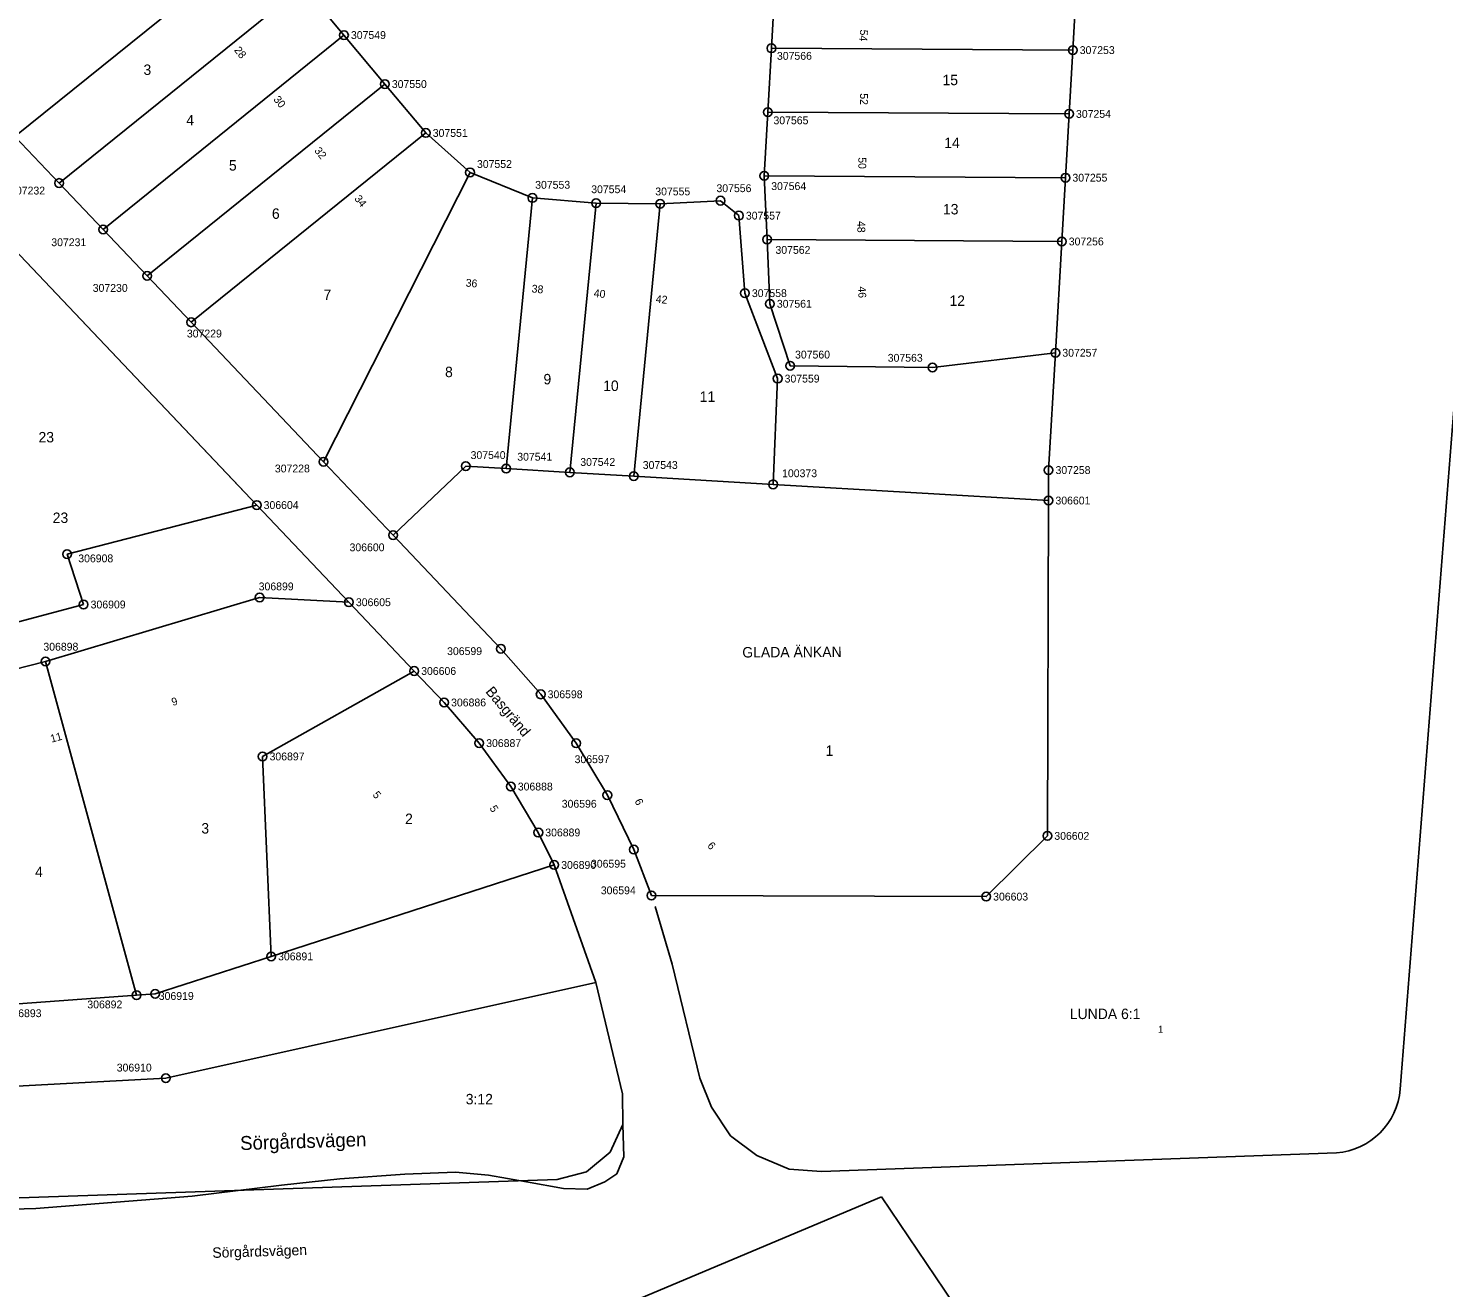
# Model space of a CAD drawing. Extents: x 141995 to 152570, y 6580184 to 6586000.
# Drawn here: x 142279.5 to 142442.1, y 6585352.4 to 6585497.2 of the extents above; entities that cross this region are included whole.
import ezdxf

# ---------------------------------------------------------------- set-up
doc = ezdxf.new("R2010")
doc.units = 0
for name, color, linetype in [('Level 10', 7, 'Continuous'), ('Level 13', 7, 'Continuous'), ('Level 40', 7, 'Continuous'), ('Level 43', 7, 'Continuous'), ('Level 5', 7, 'Continuous'), ('Level 51', 7, 'Continuous'), ('Level 53', 7, 'Continuous'), ('Level 54', 7, 'Continuous'), ('Level 55', 7, 'Continuous'), ('Level 58', 7, 'Continuous'), ('Level 59', 7, 'Continuous'), ('Level 6', 7, 'Continuous'), ('Level 7', 7, 'Continuous')]:
    doc.layers.add(name, color=color, linetype=linetype)

msp = doc.modelspace()

# ---------------------------------------------------------------- linework, layer by layer
at = {"layer": 'Level 10'}
for centre in [(142315.73, 6585496.38), (142364.84, 6585494.86), (142399.47, 6585494.64), (142320.43, 6585490.75), (142364.43, 6585487.53), (142399.04, 6585487.32), (142325.13, 6585485.13), (142282.99, 6585479.38), (142330.21, 6585480.6), (142364.02, 6585480.21), (142398.63, 6585479.99), (142337.38, 6585477.66), (142344.69, 6585477.07), (142352.05, 6585476.98), (142359, 6585477.35), (142361.11, 6585475.63), (142288.05, 6585474.04), (142364.34, 6585472.88), (142398.21, 6585472.66), (142293.11, 6585468.71), (142361.8, 6585466.72), (142364.67, 6585465.5), (142298.17, 6585463.37), (142397.47, 6585459.87), (142367, 6585458.38), (142383.35, 6585458.18), (142365.56, 6585456.9), (142313.38, 6585447.35), (142329.72, 6585446.84), (142334.37, 6585446.56), (142341.69, 6585446.13), (142349.02, 6585445.7), (142396.69, 6585446.39), (142365.03, 6585444.75), (142305.7, 6585442.37), (142396.68, 6585442.89), (142321.37, 6585438.92), (142283.91, 6585436.73), (142285.81, 6585430.94), (142306.04, 6585431.75), (142316.3, 6585431.2), (142333.76, 6585425.86), (142281.44, 6585424.4), (142323.8, 6585423.3), (142338.33, 6585420.62), (142327.24, 6585419.68), (142331.27, 6585415.01), (142342.41, 6585414.99), (142306.38, 6585413.48), (142334.9, 6585410.02), (142345.99, 6585409.03), (142338.06, 6585404.73), (142396.55, 6585404.35), (142349.04, 6585402.77), (142339.89, 6585401.01), (142351.05, 6585397.5), (142389.52, 6585397.37), (142307.36, 6585390.5), (142291.9, 6585386.04), (142294.04, 6585386.19), (142295.25, 6585376.5)]:
    msp.add_circle(centre, 0.5, dxfattribs=at)
at = {"layer": 'Level 13'}
for points in [[(142459.71, 6585662.03), (142437.09, 6585375.26)], [(142339.89, 6585401.01), (142344.67, 6585387.51)], [(142351.48, 6585396.22), (142353.42, 6585389.61)], [(142353.42, 6585389.61), (142356.62, 6585376.49)], [(142356.62, 6585376.49), (142357.95, 6585373.16)], [(142357.95, 6585373.16), (142360.14, 6585369.89)], [(142106.18, 6585355.96), (142199.95, 6585359.22), (142280.34, 6585361.53), (142298.3, 6585362.96), (142308.55, 6585364.2), (142315.26, 6585364.94), (142322.71, 6585365.48), (142328.56, 6585365.72), (142332.32, 6585365.37), (142336.72, 6585364.61), (142340.97, 6585363.81), (142343.67, 6585363.75), (142345.72, 6585364.6), (142347.07, 6585365.5), (142347.87, 6585367.45), (142347.76, 6585371.19)], [(142360.14, 6585369.89), (142363.18, 6585367.64)], [(142363.18, 6585367.64), (142366.87, 6585366.06)], [(142370.6, 6585365.8), (142429.77, 6585367.93)], [(142366.87, 6585366.06), (142370.6, 6585365.8)]]:
    msp.add_lwpolyline(points, dxfattribs=at)
msp.add_arc((142429.14, 6585375.88), 7.98, 274.4774, 355.4776, dxfattribs=at)
at = {"layer": 'Level 5'}
for points in [[(142400.41, 6585511.05), (142399.47, 6585494.64)], [(142399.47, 6585494.64), (142399.04, 6585487.32)], [(142399.04, 6585487.32), (142398.63, 6585479.99)], [(142282.99, 6585479.38), (142277.92, 6585484.71)], [(142398.63, 6585479.99), (142398.21, 6585472.66)], [(142288.05, 6585474.04), (142282.99, 6585479.38)], [(142272.2, 6585477.67), (142305.7, 6585442.37)], [(142293.11, 6585468.71), (142288.05, 6585474.04)], [(142398.21, 6585472.66), (142397.47, 6585459.87)], [(142298.17, 6585463.37), (142293.11, 6585468.71)], [(142313.38, 6585447.35), (142298.17, 6585463.37)], [(142397.47, 6585459.87), (142396.69, 6585446.39)], [(142313.38, 6585447.35), (142321.37, 6585438.92)], [(142396.69, 6585446.39), (142396.68, 6585442.89)], [(142316.3, 6585431.2), (142305.7, 6585442.37)], [(142396.68, 6585442.89), (142396.55, 6585404.35)], [(142333.76, 6585425.86), (142321.37, 6585438.92)], [(142316.3, 6585431.2), (142323.8, 6585423.3)], [(142338.33, 6585420.62), (142333.76, 6585425.86)], [(142323.8, 6585423.3), (142327.24, 6585419.68)], [(142327.24, 6585419.68), (142331.27, 6585415.01)], [(142342.41, 6585414.99), (142338.33, 6585420.62)], [(142331.27, 6585415.01), (142334.9, 6585410.02)], [(142345.99, 6585409.03), (142342.41, 6585414.99)], [(142334.9, 6585410.02), (142338.06, 6585404.73)], [(142349.04, 6585402.77), (142345.99, 6585409.03)], [(142338.06, 6585404.73), (142339.89, 6585401.01)], [(142396.55, 6585404.35), (142389.52, 6585397.37)], [(142351.05, 6585397.5), (142349.04, 6585402.77)], [(142339.89, 6585401.01), (142307.36, 6585390.5)], [(142389.52, 6585397.37), (142351.05, 6585397.5)], [(142307.36, 6585390.5), (142294.04, 6585386.19)], [(142295.25, 6585376.5), (142344.67, 6585387.51)], [(142344.67, 6585387.51), (142347.72, 6585374.7)], [(142291.9, 6585386.04), (142276.72, 6585384.95)], [(142294.04, 6585386.19), (142291.9, 6585386.04)], [(142143.25, 6585368.36), (142295.25, 6585376.5)], [(142347.72, 6585374.7), (142347.76, 6585371.19)], [(142347.76, 6585371.19), (142346.31, 6585368)], [(142346.31, 6585368), (142343.61, 6585365.74)], [(142094.06, 6585356.49), (142340.21, 6585364.86)], [(142343.61, 6585365.74), (142340.21, 6585364.86)], [(142323.06, 6585339.95), (142377.49, 6585362.87)], [(142377.49, 6585362.87), (142393.01, 6585339.88)]]:
    msp.add_lwpolyline(points, dxfattribs=at)
at = {"layer": 'Level 6'}
for points in [[(142351.05, 6585397.5), (142389.52, 6585397.37), (142396.55, 6585404.35), (142396.68, 6585442.89), (142396.69, 6585446.39), (142397.47, 6585459.87), (142398.21, 6585472.66), (142398.63, 6585479.99), (142399.04, 6585487.32), (142399.47, 6585494.64), (142400.41, 6585511.05), (142400.92, 6585519.9), (142396.06, 6585525.94), (142391.32, 6585531.82), (142386.59, 6585537.7), (142381.85, 6585543.58), (142373.89, 6585553.45), (142366.17, 6585563.06), (142361.56, 6585568.77), (142356.96, 6585574.49), (142350.69, 6585582.27), (142342.66, 6585592.25), (142323.23, 6585620.83)], [(142277.92, 6585484.71), (142282.99, 6585479.38), (142288.05, 6585474.04), (142293.11, 6585468.71), (142298.17, 6585463.37), (142313.38, 6585447.35), (142321.37, 6585438.92), (142333.76, 6585425.86), (142338.33, 6585420.62), (142342.41, 6585414.99), (142345.99, 6585409.03), (142349.04, 6585402.77), (142351.05, 6585397.5)], [(142276.72, 6585384.95), (142291.9, 6585386.04), (142294.04, 6585386.19), (142307.36, 6585390.5), (142339.89, 6585401.01), (142338.06, 6585404.73), (142334.9, 6585410.02), (142331.27, 6585415.01), (142327.24, 6585419.68), (142323.8, 6585423.3), (142316.3, 6585431.2), (142305.7, 6585442.37), (142303.68, 6585444.5), (142272.2, 6585477.67)]]:
    msp.add_lwpolyline(points, dxfattribs=at)
at = {"layer": 'Level 7'}
for points in [[(142306.32, 6585507.63), (142277.92, 6585484.71)], [(142365.27, 6585502.54), (142364.84, 6585494.86)], [(142311.03, 6585502), (142282.99, 6585479.38)], [(142315.73, 6585496.38), (142311.03, 6585502)], [(142315.73, 6585496.38), (142288.05, 6585474.04)], [(142320.43, 6585490.75), (142315.73, 6585496.38)], [(142364.84, 6585494.86), (142364.43, 6585487.53)], [(142364.84, 6585494.86), (142399.47, 6585494.64)], [(142320.43, 6585490.75), (142293.11, 6585468.71)], [(142325.13, 6585485.13), (142320.43, 6585490.75)], [(142364.43, 6585487.53), (142364.02, 6585480.21)], [(142364.43, 6585487.53), (142399.04, 6585487.32)], [(142325.13, 6585485.13), (142298.17, 6585463.37)], [(142330.21, 6585480.6), (142325.13, 6585485.13)], [(142330.21, 6585480.6), (142313.38, 6585447.35)], [(142337.38, 6585477.66), (142330.21, 6585480.6)], [(142364.02, 6585480.21), (142398.63, 6585479.99)], [(142364.02, 6585480.21), (142364.34, 6585472.88)], [(142334.37, 6585446.56), (142337.38, 6585477.66)], [(142344.69, 6585477.07), (142337.38, 6585477.66)], [(142344.69, 6585477.07), (142341.69, 6585446.13)], [(142352.05, 6585476.98), (142344.69, 6585477.07)], [(142352.05, 6585476.98), (142349.02, 6585445.7)], [(142359, 6585477.35), (142352.05, 6585476.98)], [(142361.11, 6585475.63), (142359, 6585477.35)], [(142361.8, 6585466.72), (142361.11, 6585475.63)], [(142364.34, 6585472.88), (142398.21, 6585472.66)], [(142364.34, 6585472.88), (142364.67, 6585465.5)], [(142365.56, 6585456.9), (142361.8, 6585466.72)], [(142364.67, 6585465.5), (142367, 6585458.38)], [(142383.35, 6585458.18), (142397.47, 6585459.87)], [(142365.03, 6585444.75), (142365.56, 6585456.9)], [(142367, 6585458.38), (142383.35, 6585458.18)], [(142329.72, 6585446.84), (142321.37, 6585438.92)], [(142329.72, 6585446.84), (142334.37, 6585446.56)], [(142341.69, 6585446.13), (142334.37, 6585446.56)], [(142349.02, 6585445.7), (142341.69, 6585446.13)], [(142365.03, 6585444.75), (142349.02, 6585445.7)], [(142365.03, 6585444.75), (142396.68, 6585442.89)], [(142305.7, 6585442.37), (142283.91, 6585436.73)], [(142283.91, 6585436.73), (142285.81, 6585430.94)], [(142285.81, 6585430.94), (142272.12, 6585427.31)], [(142281.44, 6585424.4), (142306.04, 6585431.75)], [(142306.04, 6585431.75), (142316.3, 6585431.2)], [(142268.19, 6585421.04), (142281.44, 6585424.4)], [(142291.9, 6585386.04), (142281.44, 6585424.4)], [(142306.38, 6585413.48), (142323.8, 6585423.3)], [(142307.36, 6585390.5), (142306.38, 6585413.48)]]:
    msp.add_lwpolyline(points, dxfattribs=at)

# ---------------------------------------------------------------- texts
at = {"layer": 'Level 40'}
for s, rotation, p in [('Basgränd', 309.9922, (142331.93, 6585420.9)), ('Sörgårdsvägen', 1.8005, (142300.62, 6585355.85))]:
    msp.add_text(s, height=1.2, rotation=rotation, dxfattribs=at).set_placement(p)
at = {"layer": 'Level 43'}
msp.add_text('Sörgårdsvägen', height=1.6, rotation=1.8005, dxfattribs=at).set_placement((142303.82, 6585368.24))
at = {"layer": 'Level 51'}
for s, rotation, p in [('3', 0.0527, (142292.69, 6585491.8)), ('15', 0.0527, (142384.5, 6585490.62)), ('4', 0.0527, (142297.6, 6585485.99)), ('14', 0.0527, (142384.7, 6585483.4)), ('5', 0.0527, (142302.51, 6585480.81)), ('6', 0.0527, (142307.45, 6585475.26)), ('13', 0.0527, (142384.55, 6585475.77)), ('7', 0.0527, (142313.38, 6585465.94)), ('12', 0.0527, (142385.3, 6585465.26)), ('8', 0.0527, (142327.34, 6585457.07)), ('9', 0.0527, (142338.65, 6585456.24)), ('10', 0.0527, (142345.51, 6585455.48)), ('11', 0.0527, (142356.6, 6585454.23)), ('23', 0.0527, (142280.63, 6585449.57)), ('1', 0.0527, (142371.06, 6585413.54)), ('2', 0.0527, (142322.75, 6585405.71)), ('3', 0.0527, (142299.34, 6585404.62)), ('4', 0.0526, (142280.24, 6585399.62))]:
    msp.add_text(s, height=1.2, rotation=rotation, dxfattribs=at).set_placement(p)
for s, height, p in [('LUNDA 6:1', 1.2, (142399.13, 6585383.3)), ('1', 0.8, (142409.27, 6585381.73))]:
    msp.add_text(s, height=height, dxfattribs=at).set_placement(p)
at = {"layer": 'Level 53'}
for s, rotation, p in [('307549', 0.0527, (142316.53, 6585495.93)), ('307566', 0.0527, (142365.48, 6585493.54)), ('307253', 0.0527, (142400.27, 6585494.2)), ('307550', 0.0527, (142321.23, 6585490.3)), ('307254', 0.0527, (142399.84, 6585486.87)), ('307565', 0.0527, (142365.08, 6585486.13)), ('307551', 0.0527, (142325.93, 6585484.68)), ('307552', 0.0527, (142331.01, 6585481.11)), ('307553', 0.0527, (142337.7, 6585478.72)), ('307255', 0.0527, (142399.43, 6585479.54)), ('307232', 0.0527, (142277.37, 6585478.06)), ('307554', 0.0527, (142344.14, 6585478.21)), ('307555', 0.0527, (142351.5, 6585477.96)), ('307556', 0.0527, (142358.53, 6585478.33)), ('307564', 0.0527, (142364.82, 6585478.57)), ('307557', 0.0527, (142361.91, 6585475.18)), ('307256', 0.0527, (142399.01, 6585472.21)), ('307231', 0.0527, (142282.1, 6585472.12)), ('307562', 0.0527, (142365.31, 6585471.24)), ('307230', 0.0527, (142286.86, 6585466.87)), ('307558', 0.0527, (142362.6, 6585466.27)), ('307561', 0.0527, (142365.47, 6585465.05)), ('307229', 0.0527, (142297.68, 6585461.63)), ('307560', 0.0527, (142367.56, 6585459.21)), ('307257', 0.0527, (142398.27, 6585459.42)), ('307563', 0.0527, (142378.21, 6585458.84)), ('307559', 0.0527, (142366.36, 6585456.45)), ('307540', 0.0527, (142330.28, 6585447.66)), ('307541', 0.0527, (142335.64, 6585447.47)), ('307542', 0.0527, (142342.88, 6585446.87)), ('307543', 0.0527, (142350.06, 6585446.52)), ('307228', 0.0527, (142307.79, 6585446.12)), ('100373', 0.0527, (142366.07, 6585445.57)), ('307258', 0.0527, (142397.49, 6585445.94)), ('306604', 0.0527, (142306.5, 6585441.92)), ('306601', 0.0527, (142397.48, 6585442.44)), ('306600', 0.0527, (142316.37, 6585437.06)), ('306908', 0.0527, (142285.2, 6585435.79)), ('306899', 0.0527, (142305.93, 6585432.57)), ('306909', 0.0527, (142286.62, 6585430.49)), ('306605', 0.0527, (142317.1, 6585430.75)), ('306898', 0.0527, (142281.19, 6585425.64)), ('306599', 0.0527, (142327.58, 6585425.13)), ('306606', 0.0527, (142324.6, 6585422.85)), ('306598', 0.0527, (142339.13, 6585420.17)), ('306886', 0.0527, (142328.04, 6585419.23)), ('306887', 0.0527, (142332.07, 6585414.56)), ('306897', 0.0527, (142307.18, 6585413.03)), ('306597', 0.0527, (142342.23, 6585412.71)), ('306888', 0.0527, (142335.7, 6585409.57)), ('306596', 0.0527, (142340.75, 6585407.59)), ('306889', 0.0527, (142338.86, 6585404.29)), ('306602', 0.0527, (142397.35, 6585403.9)), ('306595', 0.0527, (142344.11, 6585400.7)), ('306890', 0.0527, (142340.69, 6585400.56)), ('306594', 0.0526, (142345.24, 6585397.64)), ('306603', 0.0527, (142390.32, 6585396.92)), ('306891', 0.0526, (142308.16, 6585390.05)), ('306892', 0.0526, (142286.24, 6585384.53)), ('306919', 0.0526, (142294.45, 6585385.5)), ('306893', 0.0526, (142276.96, 6585383.52)), ('306910', 0.0526, (142289.62, 6585377.27))]:
    msp.add_text(s, height=0.9, rotation=rotation, dxfattribs=at).set_placement(p)
at = {"layer": 'Level 54'}
for s, rotation, p in [('54', 265.6273, (142375.04, 6585497.04)), ('28', 308.8752, (142303.05, 6585494.63)), ('30', 308.8752, (142307.57, 6585488.96)), ('52', 270.2693, (142375.03, 6585489.69)), ('32', 308.8752, (142312.27, 6585483.07)), ('50', 270.2813, (142374.83, 6585482.34)), ('34', 308.8752, (142316.87, 6585477.56)), ('48', 270.8043, (142374.71, 6585475.01)), ('36', 354.5437, (142329.68, 6585467.49)), ('38', 354.5437, (142337.26, 6585466.81)), ('40', 354.5437, (142344.4, 6585466.29)), ('46', 271.4473, (142374.81, 6585467.49)), ('42', 354.5437, (142351.52, 6585465.62)), ('9', 17.5245, (142296.07, 6585419.27)), ('11', 15.3446, (142282.13, 6585415.06)), ('5', 308.9372, (142318.96, 6585409.05)), ('6', 314.0964, (142357.41, 6585403.15))]:
    msp.add_text(s, height=0.9, rotation=rotation, dxfattribs=at).set_placement(p)
at = {"layer": 'Level 55'}
for s, rotation, p in [('6', 295.9527, (142349.09, 6585408.37)), ('5', 300.9029, (142332.42, 6585407.54))]:
    msp.add_text(s, height=0.9, rotation=rotation, dxfattribs=at).set_placement(p)
at = {"layer": 'Level 58'}
msp.add_text('GLADA ÄNKAN', height=1.2, rotation=0.2627, dxfattribs=at).set_placement((142361.5, 6585424.85))
at = {"layer": 'Level 59'}
for s, rotation, p in [('23', 0.0527, (142282.26, 6585440.31)), ('3:12', 0.0526, (142329.72, 6585373.5))]:
    msp.add_text(s, height=1.2, rotation=rotation, dxfattribs=at).set_placement(p)

doc.saveas('drawing.dxf')
